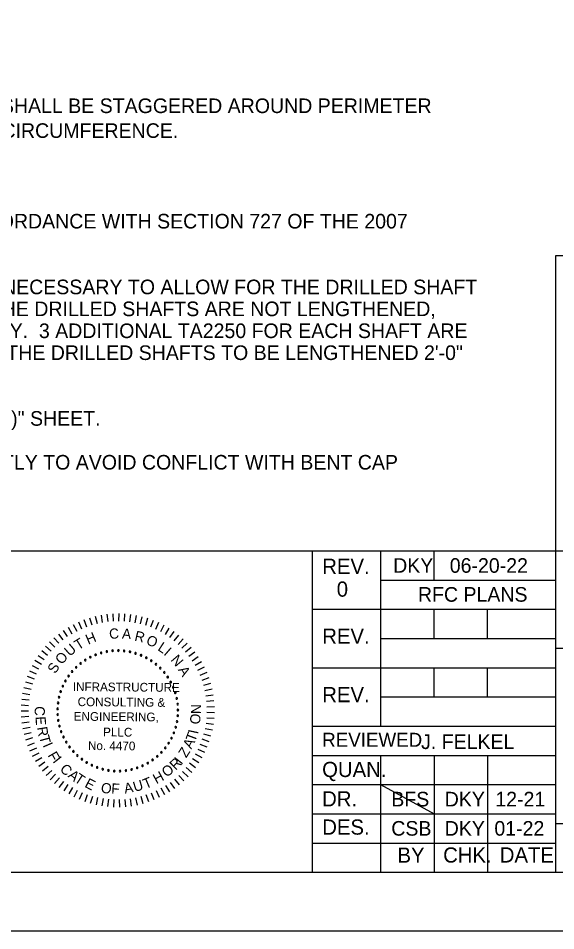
# Model space of a CAD drawing. Extents: x -225.1 to -152.9, y -16.8 to 27.2.
# Drawn here: x -174.12 to -164.91, y -16.78 to -1.16 of the extents above; entities that cross this region are included whole.
import ezdxf

# ---------------------------------------------------------------- set-up
doc = ezdxf.new("R2010")
doc.units = 0
for name, color, linetype in [('BR_BORDER LINES', 7, 'Continuous'), ('BR_TEXT', 7, 'Continuous'), ('Level 31', 7, 'Continuous')]:
    doc.layers.add(name, color=color, linetype=linetype)

msp = doc.modelspace()

# ---------------------------------------------------------------- linework, layer by layer
at = {"layer": 'BR_BORDER LINES'}
for p, q in [((-164.912, -15.776), (-164.912, -5.223)), ((-164.912, -5.223), (-154.078, -5.223)), ((-179.809, -10.276), (-169.079, -10.276)), ((-169.079, -15.776), (-169.079, -10.276)), ((-169.079, -10.276), (-154.078, -10.276)), ((-167.912, -10.276), (-167.912, -13.276)), ((-166.996, -10.776), (-166.996, -10.276)), ((-167.912, -10.776), (-164.912, -10.776)), ((-169.079, -11.276), (-164.912, -11.276)), ((-166.996, -11.776), (-166.996, -11.276)), ((-166.079, -11.776), (-166.079, -11.276)), ((-167.912, -11.776), (-164.912, -11.776)), ((-164.912, -11.943), (-164.912, -11.943)), ((-164.912, -11.943), (-154.078, -11.943)), ((-169.079, -12.276), (-164.912, -12.276)), ((-166.996, -12.776), (-166.996, -12.276)), ((-166.079, -12.776), (-166.079, -12.276)), ((-167.912, -12.776), (-164.912, -12.776)), ((-169.079, -13.276), (-164.912, -13.276)), ((-169.079, -13.776), (-164.912, -13.776)), ((-167.912, -13.776), (-167.912, -15.776)), ((-166.996, -13.776), (-166.996, -15.776)), ((-166.079, -13.776), (-166.079, -15.776)), ((-169.079, -14.276), (-164.912, -14.276)), ((-169.079, -14.776), (-164.912, -14.776)), ((-164.912, -14.943), (-154.078, -14.943)), ((-169.079, -15.276), (-164.912, -15.276)), ((-221.411, -15.776), (-154.078, -15.776))]:
    msp.add_line(p, q, dxfattribs=at)
at = {"layer": 'BR_TEXT'}
for p, q in [((-172.797, -11.395), (-172.767, -11.518)), ((-172.698, -11.374), (-172.676, -11.5)), ((-172.598, -11.36), (-172.583, -11.486)), ((-172.497, -11.351), (-172.49, -11.479)), ((-172.396, -11.349), (-172.397, -11.477)), ((-172.295, -11.353), (-172.304, -11.48)), ((-172.195, -11.364), (-172.211, -11.49)), ((-172.095, -11.38), (-172.119, -11.505)), ((-173.174, -11.535), (-173.115, -11.648)), ((-173.083, -11.492), (-173.031, -11.608)), ((-172.99, -11.453), (-172.945, -11.573)), ((-172.894, -11.421), (-172.857, -11.543)), ((-171.997, -11.402), (-172.028, -11.525)), ((-171.9, -11.43), (-171.939, -11.552)), ((-171.805, -11.465), (-171.851, -11.583)), ((-171.712, -11.504), (-171.766, -11.62)), ((-171.622, -11.55), (-171.682, -11.662)), ((-173.429, -11.699), (-173.35, -11.799)), ((-173.347, -11.639), (-173.275, -11.744)), ((-173.262, -11.584), (-173.197, -11.694)), ((-171.535, -11.601), (-171.602, -11.709)), ((-171.451, -11.657), (-171.524, -11.761)), ((-173.58, -11.832), (-173.49, -11.922)), ((-173.507, -11.763), (-173.422, -11.858)), ((-171.37, -11.718), (-171.45, -11.817)), ((-171.294, -11.784), (-171.38, -11.878)), ((-171.221, -11.854), (-171.313, -11.943)), ((-173.714, -11.983), (-173.614, -12.061)), ((-173.65, -11.905), (-173.554, -11.99)), ((-171.154, -11.929), (-171.25, -12.012)), ((-171.09, -12.008), (-171.192, -12.085)), ((-173.829, -12.149), (-173.72, -12.215)), ((-173.774, -12.064), (-173.669, -12.136)), ((-171.032, -12.09), (-171.138, -12.161)), ((-170.979, -12.176), (-171.089, -12.24)), ((-173.923, -12.328), (-173.806, -12.38)), ((-173.878, -12.237), (-173.766, -12.296)), ((-170.931, -12.265), (-171.045, -12.322)), ((-173.961, -12.421), (-173.842, -12.466)), ((-170.889, -12.357), (-171.006, -12.407)), ((-170.852, -12.451), (-170.972, -12.493)), ((-174.021, -12.614), (-173.897, -12.644)), ((-173.994, -12.517), (-173.872, -12.554)), ((-170.821, -12.547), (-170.943, -12.582)), ((-170.796, -12.645), (-170.92, -12.672)), ((-174.041, -12.713), (-173.916, -12.735)), ((-170.777, -12.744), (-170.903, -12.764)), ((-174.065, -12.913), (-173.938, -12.92)), ((-174.056, -12.813), (-173.93, -12.827)), ((-170.764, -12.844), (-170.891, -12.856)), ((-170.758, -12.945), (-170.885, -12.949)), ((-174.067, -13.014), (-173.94, -13.013)), ((-174.064, -13.115), (-173.937, -13.107)), ((-170.757, -13.046), (-170.884, -13.043)), ((-174.054, -13.216), (-173.927, -13.199)), ((-170.774, -13.247), (-170.9, -13.228)), ((-170.763, -13.146), (-170.889, -13.136)), ((-174.038, -13.315), (-173.913, -13.291)), ((-174.016, -13.414), (-173.893, -13.382)), ((-170.816, -13.444), (-170.939, -13.411)), ((-170.792, -13.346), (-170.917, -13.32)), ((-173.988, -13.511), (-173.867, -13.472)), ((-173.954, -13.606), (-173.836, -13.56)), ((-170.846, -13.541), (-170.966, -13.5)), ((-173.915, -13.699), (-173.799, -13.645)), ((-173.87, -13.789), (-173.757, -13.729)), ((-170.922, -13.727), (-171.037, -13.672)), ((-170.881, -13.635), (-170.999, -13.587)), ((-173.819, -13.877), (-173.711, -13.809)), ((-173.763, -13.961), (-173.659, -13.887)), ((-171.022, -13.903), (-171.129, -13.834)), ((-170.969, -13.817), (-171.08, -13.754)), ((-173.702, -14.041), (-173.603, -13.962)), ((-173.637, -14.118), (-173.543, -14.032)), ((-171.141, -14.066), (-171.239, -13.984)), ((-171.079, -13.986), (-171.182, -13.911)), ((-173.567, -14.191), (-173.478, -14.099)), ((-173.492, -14.259), (-173.409, -14.162)), ((-171.356, -14.279), (-171.437, -14.181)), ((-171.28, -14.213), (-171.367, -14.12)), ((-171.208, -14.141), (-171.301, -14.054)), ((-173.414, -14.323), (-173.337, -14.221)), ((-173.331, -14.381), (-173.261, -14.275)), ((-173.246, -14.435), (-173.182, -14.325)), ((-171.605, -14.45), (-171.667, -14.339)), ((-171.518, -14.398), (-171.587, -14.291)), ((-171.435, -14.341), (-171.51, -14.239)), ((-173.157, -14.483), (-173.1, -14.369)), ((-173.066, -14.526), (-173.015, -14.408)), ((-172.972, -14.563), (-172.929, -14.443)), ((-172.876, -14.594), (-172.84, -14.472)), ((-172.778, -14.619), (-172.75, -14.495)), ((-172.679, -14.638), (-172.658, -14.513)), ((-172.176, -14.643), (-172.194, -14.517)), ((-172.076, -14.626), (-172.102, -14.501)), ((-171.978, -14.602), (-172.012, -14.479)), ((-171.882, -14.573), (-171.923, -14.452)), ((-171.787, -14.538), (-171.835, -14.42)), ((-171.695, -14.497), (-171.75, -14.382)), ((-172.579, -14.652), (-172.566, -14.525)), ((-172.478, -14.659), (-172.473, -14.532)), ((-172.377, -14.66), (-172.38, -14.532)), ((-172.276, -14.655), (-172.287, -14.528))]:
    msp.add_line(p, q, dxfattribs=at)
for centre, start, end in [((-172.696, -12.022), 16.1422, 196.1422), ((-172.696, -12.022), 196.1422, 16.1422), ((-172.599, -11.999), 10.6038, 190.6038), ((-172.599, -11.999), 190.6038, 10.6038), ((-172.501, -11.985), 5.0653, 185.0653), ((-172.501, -11.985), 185.0653, 5.0653), ((-172.401, -11.982), 359.5268, 179.5268), ((-172.401, -11.982), 179.5268, 359.5268), ((-172.302, -11.988), 173.9884, 353.9884), ((-172.302, -11.988), 353.9884, 173.9884), ((-172.203, -12.003), 348.4499, 168.4499), ((-172.203, -12.003), 168.4499, 348.4499), ((-172.107, -12.028), 342.9114, 162.9114), ((-172.968, -12.145), 32.7576, 212.7576), ((-172.968, -12.145), 212.7576, 32.7576), ((-172.882, -12.095), 27.2191, 207.2191), ((-172.882, -12.095), 207.2191, 27.2191), ((-172.791, -12.054), 21.6807, 201.6807), ((-172.791, -12.054), 201.6807, 21.6807), ((-172.107, -12.028), 162.9114, 342.9114), ((-172.013, -12.062), 157.373, 337.373), ((-172.013, -12.062), 337.373, 157.373), ((-171.923, -12.105), 151.8345, 331.8345), ((-171.923, -12.105), 331.8345, 151.8345), ((-171.838, -12.156), 146.2961, 326.2961), ((-171.838, -12.156), 326.2961, 146.2961), ((-173.193, -12.34), 49.373, 229.373), ((-173.193, -12.34), 229.373, 49.373), ((-173.124, -12.268), 43.8345, 223.8345), ((-173.124, -12.268), 223.8345, 43.8345), ((-173.049, -12.202), 38.2961, 218.2961), ((-173.049, -12.202), 218.2961, 38.2961), ((-171.758, -12.216), 140.7576, 320.7576), ((-171.758, -12.216), 320.7576, 140.7576), ((-171.684, -12.282), 135.2191, 315.2191), ((-171.684, -12.282), 315.2191, 135.2191), ((-173.308, -12.503), 60.4499, 240.4499), ((-173.308, -12.503), 240.4499, 60.4499), ((-173.254, -12.418), 54.9114, 234.9114), ((-173.254, -12.418), 234.9114, 54.9114), ((-171.616, -12.356), 129.6807, 309.6807), ((-171.616, -12.356), 309.6807, 129.6807), ((-171.557, -12.436), 124.1422, 304.1422), ((-171.557, -12.436), 304.1422, 124.1422), ((-173.353, -12.591), 65.9884, 245.9884), ((-173.353, -12.591), 245.9884, 65.9884), ((-171.505, -12.521), 118.6038, 298.6038), ((-171.505, -12.521), 298.6038, 118.6038), ((-171.462, -12.611), 113.0653, 293.0653), ((-171.462, -12.611), 293.0653, 113.0653), ((-173.416, -12.78), 77.0653, 257.0653), ((-173.416, -12.78), 257.0653, 77.0653), ((-173.389, -12.684), 71.5268, 251.5268), ((-173.389, -12.684), 251.5268, 71.5268), ((-171.427, -12.704), 107.5268, 287.5268), ((-171.427, -12.704), 287.5268, 107.5268), ((-171.402, -12.801), 101.9884, 281.9884), ((-171.402, -12.801), 281.9884, 101.9884), ((-173.434, -12.878), 82.6038, 262.6038), ((-173.434, -12.878), 262.6038, 82.6038), ((-171.386, -12.899), 96.4499, 276.4499), ((-171.386, -12.899), 276.4499, 96.4499), ((-173.442, -12.978), 88.1422, 268.1422), ((-173.441, -13.077), 93.6807, 273.6807), ((-173.442, -12.978), 268.1422, 88.1422), ((-173.441, -13.077), 273.6807, 93.6807), ((-171.384, -13.098), 85.373, 265.373), ((-171.38, -12.999), 90.9114, 270.9114), ((-171.384, -13.098), 265.373, 85.373), ((-171.38, -12.999), 270.9114, 90.9114), ((-173.43, -13.176), 99.2191, 279.2191), ((-173.43, -13.176), 279.2191, 99.2191), ((-173.409, -13.274), 104.7576, 284.7576), ((-173.409, -13.274), 284.7576, 104.7576), ((-171.397, -13.197), 79.8345, 259.8345), ((-171.397, -13.197), 259.8345, 79.8345), ((-173.38, -13.369), 110.2961, 290.2961), ((-173.38, -13.369), 290.2961, 110.2961), ((-171.451, -13.389), 68.7576, 248.7576), ((-171.451, -13.389), 248.7576, 68.7576), ((-171.419, -13.294), 74.2961, 254.2961), ((-171.419, -13.294), 254.2961, 74.2961), ((-173.341, -13.461), 115.8345, 295.8345), ((-173.341, -13.461), 295.8345, 115.8345), ((-173.293, -13.548), 121.373, 301.373), ((-173.293, -13.548), 301.373, 121.373), ((-171.541, -13.566), 57.6807, 237.6807), ((-171.541, -13.566), 237.6807, 57.6807), ((-171.492, -13.48), 63.2191, 243.2191), ((-171.492, -13.48), 243.2191, 63.2191), ((-173.237, -13.631), 126.9114, 306.9114), ((-173.237, -13.631), 306.9114, 126.9114), ((-173.174, -13.708), 132.4499, 312.4499), ((-173.174, -13.708), 312.4499, 132.4499), ((-171.664, -13.723), 46.6038, 226.6038), ((-171.664, -13.723), 226.6038, 46.6038), ((-171.599, -13.648), 52.1422, 232.1422), ((-171.599, -13.648), 232.1422, 52.1422), ((-173.103, -13.778), 137.9884, 317.9884), ((-173.103, -13.778), 317.9884, 137.9884), ((-173.026, -13.841), 143.5268, 323.5268), ((-173.026, -13.841), 323.5268, 143.5268), ((-172.944, -13.897), 149.0653, 329.0653), ((-172.944, -13.897), 329.0653, 149.0653), ((-171.898, -13.907), 29.9884, 209.9884), ((-171.814, -13.854), 35.5268, 215.5268), ((-171.814, -13.854), 215.5268, 35.5268), ((-171.736, -13.792), 41.0653, 221.0653), ((-171.736, -13.792), 221.0653, 41.0653), ((-172.856, -13.944), 154.6038, 334.6038), ((-172.856, -13.944), 334.6038, 154.6038), ((-172.764, -13.982), 160.1422, 340.1422), ((-172.764, -13.982), 340.1422, 160.1422), ((-172.669, -14.012), 165.6807, 345.6807), ((-172.669, -14.012), 345.6807, 165.6807), ((-172.571, -14.032), 351.2191, 171.2191), ((-172.571, -14.032), 171.2191, 351.2191), ((-172.472, -14.043), 356.7576, 176.7576), ((-172.472, -14.043), 176.7576, 356.7576), ((-172.372, -14.044), 2.2961, 182.2961), ((-172.372, -14.044), 182.2961, 2.2961), ((-172.273, -14.035), 7.8345, 187.8345), ((-172.273, -14.035), 187.8345, 7.8345), ((-172.175, -14.017), 13.373, 193.373), ((-172.175, -14.017), 193.373, 13.373), ((-172.079, -13.989), 18.9114, 198.9114), ((-172.079, -13.989), 198.9114, 18.9114), ((-171.987, -13.953), 24.4499, 204.4499), ((-171.987, -13.953), 204.4499, 24.4499), ((-171.898, -13.907), 209.9884, 29.9884)]:
    msp.add_arc(centre, 0.014, start, end, dxfattribs=at)
at = {"layer": 'Level 31'}
msp.add_line((-167.912, -14.276), (-166.996, -14.776), dxfattribs=at)
msp.add_lwpolyline([(-225.077, -16.776), (-153.077, -16.776), (-153.077, 27.224), (-225.077, 27.224)], close=True, dxfattribs=at)

# ---------------------------------------------------------------- texts
at = {"layer": 'BR_TEXT'}
for s, height, p in [('THE LOCATION OF WELDED SPLICES ON ADJACENT HOOPS SHALL BE STAGGERED AROUND PERIMETER', 0.25, (-184.313, -2.785)), (' OF THE HOOP CIRCUMFERENCE.', 0.25, (-176.892, -3.21)), ('CROSSHOLE SONIC LOGGING IS TO BE CONDUCTED IN ACCORDANCE WITH SECTION 727 OF THE 2007 ', 0.25, (-184.313, -4.76)), ('A32 BARS IN DRILLED SHAFT  ARE DETAILED LONGER THAN NECESSARY TO ALLOW FOR THE DRILLED SHAFT ', 0.25, (-184.313, -5.885)), ('TO BE LENGTHENED 2\'-0" WITHOUT ADDITIONAL STEEL.  IF THE DRILLED SHAFTS ARE NOT LENGTHENED, ', 0.25, (-184.313, -6.26)), ('THESE BARS SHALL BE CUT OFF IN THE FIELD AS NECESSARY.  3 ADDITIONAL TA2250 FOR EACH SHAFT ARE ', 0.25, (-184.313, -6.635)), ('PROVIDED IN THE REINFORCING SCHEDULE TO ALLOW FOR THE DRILLED SHAFTS TO BE LENGTHENED 2\'-0" ', 0.25, (-184.313, -7.01)), ('FOR TABLE OF VARIABLES, SEE "INTERIOR BENT DETAILS (14)" SHEET.', 0.25, (-184.313, -8.135)), ('HOOP REINFORCING IN BENT CAP MAY BE ADJUSTED SLIGHTLY TO AVOID CONFLICT WITH BENT CAP', 0.25, (-184.313, -8.885)), ('REV.', 0.26, (-168.91, -10.67)), ('DKY', 0.25, (-167.696, -10.651)), ('06-20-22', 0.25, (-166.727, -10.651)), ('0', 0.26, (-168.662, -11.06)), ('RFC PLANS', 0.25, (-167.272, -11.146)), ('REV.', 0.26, (-168.91, -11.865)), ('REV.', 0.26, (-168.91, -12.865)), ('REVIEWED', 0.24, (-168.911, -13.629)), ('J. FELKEL', 0.25, (-167.218, -13.667)), ('QUAN.', 0.26, (-168.912, -14.146)), ('DR.', 0.26, (-168.912, -14.649)), ('BFS', 0.25, (-167.728, -14.649)), ('DKY', 0.25, (-166.813, -14.649)), ('12-21', 0.25, (-165.947, -14.649)), ('DES.', 0.26, (-168.91, -15.132)), ('CSB', 0.25, (-167.728, -15.149)), ('DKY', 0.25, (-166.813, -15.149)), ('01-22', 0.25, (-165.963, -15.149)), ('BY', 0.26, (-167.622, -15.612)), ('CHK.', 0.26, (-166.84, -15.61)), ('DATE', 0.26, (-165.87, -15.609))]:
    msp.add_text(s, height=height, dxfattribs=at).set_placement(p)
for s, height, rotation, p in [('H', 0.174, 22.7882, (-172.918, -11.883)), ('C', 0.174, 4.7281, (-172.552, -11.785)), ('A', 0.174, 355.6981, (-172.343, -11.775)), ('R', 0.174, 346.6681, (-172.135, -11.809)), ('U', 0.174, 40.8482, (-173.234, -12.091)), ('T', 0.174, 31.8182, (-173.087, -11.979)), ('O', 0.174, 337.638, (-171.939, -11.868)), ('L', 0.174, 327.108, (-171.741, -11.969)), ('O', 0.174, 49.8782, (-173.368, -12.233)), ('I', 0.174, 319.578, (-171.636, -12.045)), ('N', 0.174, 310.548, (-171.515, -12.146)), ('S', 0.174, 58.9083, (-173.479, -12.389)), ('A', 0.174, 301.5179, (-171.384, -12.311)), ('INFRASTRUCTURE', 0.14954, 359.5268, (-173.182, -12.674)), ('CONSULTING &', 0.14954, 359.5268, (-173.099, -12.932)), ('C', 0.174, 267.025, (-173.829, -12.929)), ('N', 0.174, 89.2085, (-170.986, -13.069)), ('ENGINEERING,', 0.14954, 359.5268, (-173.166, -13.182)), ('O', 0.174, 83.2085, (-171.008, -13.252)), ('E', 0.174, 273.025, (-173.82, -13.112)), ('R', 0.174, 279.025, (-173.794, -13.297)), ('T', 0.174, 285.025, (-173.76, -13.454)), ('PLLC', 0.1495, 359.5268, (-172.663, -13.45)), ('T', 0.174, 69.3954, (-171.091, -13.555)), ('I', 0.174, 77.9093, (-171.039, -13.42)), ('I', 0.174, 293.7713, (-173.7, -13.601)), ('No. 4470', 0.1495, 359.5268, (-172.922, -13.683)), ('A', 0.174, 63.3954, (-171.152, -13.676)), ('F', 0.174, 299.7713, (-173.618, -13.773)), ('Z', 0.174, 57.3954, (-171.24, -13.828)), ('I', 0.174, 308.5268, (-173.534, -13.88)), ('R', 0.174, 44.5268, (-171.421, -14.038)), ('I', 0.174, 52.3339, (-171.322, -13.944)), ('C', 0.174, 314.5268, (-173.415, -14.021)), ('A', 0.174, 320.5268, (-173.277, -14.138)), ('H', 0.174, 28.5268, (-171.75, -14.27)), ('O', 0.174, 38.5268, (-171.574, -14.158)), ('T', 0.174, 326.5268, (-173.168, -14.215)), ('E', 0.174, 332.5268, (-172.991, -14.31)), ('U', 0.174, 16.5268, (-172.12, -14.403)), ('T', 0.174, 22.5268, (-171.936, -14.354)), ('O', 0.174, 350.5268, (-172.71, -14.408)), ('F', 0.174, 356.5268, (-172.527, -14.426)), ('A', 0.174, 10.5268, (-172.288, -14.43))]:
    msp.add_text(s, height=height, rotation=rotation, dxfattribs=at).set_placement(p)

doc.saveas('drawing.dxf')
